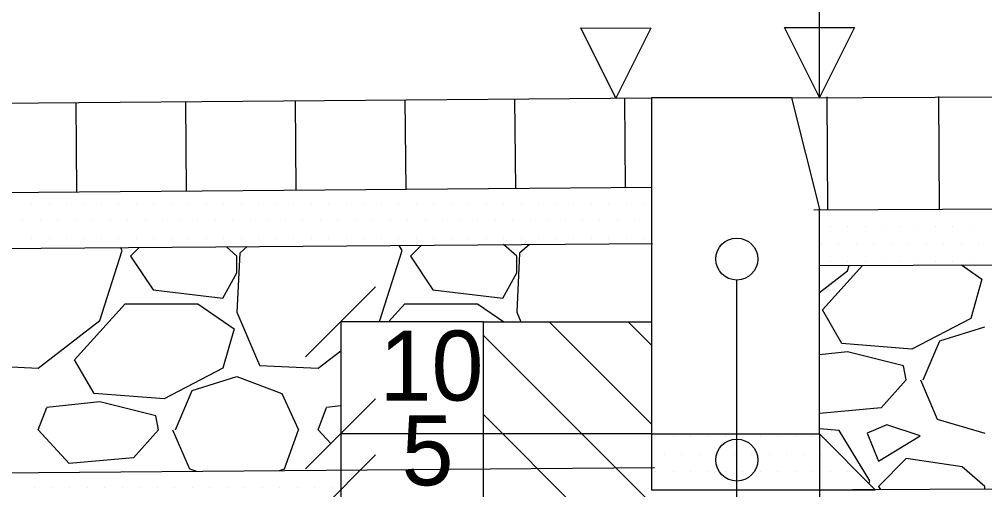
# Model space of a CAD drawing. Extents: x -219625893 to 7498339, y 5791790 to 5792761.
# Drawn here: x 7495350.16 to 7495367.41, y 5791866.2 to 5791874.6 of the extents above; entities that cross this region are included whole.
import ezdxf

# ---------------------------------------------------------------- set-up
doc = ezdxf.new("R2010")
doc.units = 0
for name, color, linetype in [('D_kons_wyp_kruszywo_lamane', 7, 'Continuous'), ('D_kons_wyp_podsypka_cem-piask', 7, 'Continuous'), ('D_kons_wyp_pospolka', 7, 'Continuous'), ('D_robocze_1', 7, 'Continuous'), ('D_wymiary_500', 7, 'Continuous'), ('Level 1', 7, 'Continuous'), ('Level 10', 7, 'Continuous'), ('Level 8', 7, 'Continuous'), ('wymiary', 7, 'Continuous')]:
    doc.layers.add(name, color=color, linetype=linetype)

msp = doc.modelspace()

# ---------------------------------------------------------------- linework, layer by layer
at = {"layer": 'D_kons_wyp_kruszywo_lamane'}
msp.add_line((7495364.582, 5791867.09), (7495364.567, 5791867.091), dxfattribs=at)
at = {"layer": 'D_kons_wyp_podsypka_cem-piask'}
for p, q in [((7495350.383, 5791871.318), (7495350.383, 5791871.318)), ((7495350.695, 5791871.318), (7495350.695, 5791871.318)), ((7495351.008, 5791871.318), (7495351.008, 5791871.318)), ((7495351.32, 5791871.318), (7495351.32, 5791871.318)), ((7495351.633, 5791871.318), (7495351.633, 5791871.318)), ((7495351.945, 5791871.318), (7495351.945, 5791871.318)), ((7495352.258, 5791871.318), (7495352.258, 5791871.318)), ((7495352.57, 5791871.318), (7495352.57, 5791871.318)), ((7495352.883, 5791871.318), (7495352.883, 5791871.318)), ((7495353.195, 5791871.318), (7495353.195, 5791871.318)), ((7495353.508, 5791871.318), (7495353.508, 5791871.318)), ((7495353.82, 5791871.318), (7495353.82, 5791871.318)), ((7495354.133, 5791871.318), (7495354.133, 5791871.318)), ((7495354.445, 5791871.318), (7495354.445, 5791871.318)), ((7495354.758, 5791871.318), (7495354.758, 5791871.318)), ((7495355.07, 5791871.318), (7495355.07, 5791871.318)), ((7495355.383, 5791871.318), (7495355.383, 5791871.318)), ((7495355.695, 5791871.318), (7495355.695, 5791871.318)), ((7495356.008, 5791871.318), (7495356.008, 5791871.318)), ((7495356.32, 5791871.318), (7495356.32, 5791871.318)), ((7495356.633, 5791871.318), (7495356.633, 5791871.318)), ((7495356.945, 5791871.318), (7495356.945, 5791871.318)), ((7495357.258, 5791871.318), (7495357.258, 5791871.318)), ((7495357.57, 5791871.318), (7495357.57, 5791871.318)), ((7495357.883, 5791871.318), (7495357.883, 5791871.318)), ((7495358.195, 5791871.318), (7495358.195, 5791871.318)), ((7495358.508, 5791871.318), (7495358.508, 5791871.318)), ((7495358.82, 5791871.318), (7495358.82, 5791871.318)), ((7495359.133, 5791871.318), (7495359.133, 5791871.318)), ((7495359.445, 5791871.318), (7495359.445, 5791871.318)), ((7495359.758, 5791871.318), (7495359.758, 5791871.318)), ((7495360.07, 5791871.318), (7495360.07, 5791871.318)), ((7495360.383, 5791871.318), (7495360.383, 5791871.318)), ((7495360.695, 5791871.318), (7495360.695, 5791871.318)), ((7495361.008, 5791871.318), (7495361.008, 5791871.318)), ((7495361.32, 5791871.318), (7495361.32, 5791871.318)), ((7495364.494, 5791871.207), (7495364.494, 5791871.207)), ((7495364.807, 5791871.207), (7495364.807, 5791871.207)), ((7495365.119, 5791871.207), (7495365.119, 5791871.207)), ((7495365.432, 5791871.207), (7495365.432, 5791871.207)), ((7495365.744, 5791871.207), (7495365.744, 5791871.207)), ((7495366.057, 5791871.207), (7495366.057, 5791871.207)), ((7495366.369, 5791871.207), (7495366.369, 5791871.207)), ((7495366.682, 5791871.207), (7495366.682, 5791871.207)), ((7495366.994, 5791871.207), (7495366.994, 5791871.207)), ((7495367.307, 5791871.207), (7495367.307, 5791871.207)), ((7495350.227, 5791871.005), (7495350.227, 5791871.005)), ((7495350.539, 5791871.005), (7495350.539, 5791871.005)), ((7495350.852, 5791871.005), (7495350.852, 5791871.005)), ((7495351.164, 5791871.005), (7495351.164, 5791871.005)), ((7495351.477, 5791871.005), (7495351.477, 5791871.005)), ((7495351.789, 5791871.005), (7495351.789, 5791871.005)), ((7495352.102, 5791871.005), (7495352.102, 5791871.005)), ((7495352.414, 5791871.005), (7495352.414, 5791871.005)), ((7495352.727, 5791871.005), (7495352.727, 5791871.005)), ((7495353.039, 5791871.005), (7495353.039, 5791871.005)), ((7495353.352, 5791871.005), (7495353.352, 5791871.005)), ((7495353.664, 5791871.005), (7495353.664, 5791871.005)), ((7495353.977, 5791871.005), (7495353.977, 5791871.005)), ((7495354.289, 5791871.005), (7495354.289, 5791871.005)), ((7495354.602, 5791871.005), (7495354.602, 5791871.005)), ((7495354.914, 5791871.005), (7495354.914, 5791871.005)), ((7495355.227, 5791871.005), (7495355.227, 5791871.005)), ((7495355.539, 5791871.005), (7495355.539, 5791871.005)), ((7495355.852, 5791871.005), (7495355.852, 5791871.005)), ((7495356.164, 5791871.005), (7495356.164, 5791871.005)), ((7495356.477, 5791871.005), (7495356.477, 5791871.005)), ((7495356.789, 5791871.005), (7495356.789, 5791871.005)), ((7495357.102, 5791871.005), (7495357.102, 5791871.005)), ((7495357.414, 5791871.005), (7495357.414, 5791871.005)), ((7495357.727, 5791871.005), (7495357.727, 5791871.005)), ((7495358.039, 5791871.005), (7495358.039, 5791871.005)), ((7495358.352, 5791871.005), (7495358.352, 5791871.005)), ((7495358.664, 5791871.005), (7495358.664, 5791871.005)), ((7495358.977, 5791871.005), (7495358.977, 5791871.005)), ((7495359.289, 5791871.005), (7495359.289, 5791871.005)), ((7495359.602, 5791871.005), (7495359.602, 5791871.005)), ((7495359.914, 5791871.005), (7495359.914, 5791871.005)), ((7495360.227, 5791871.005), (7495360.227, 5791871.005)), ((7495360.539, 5791871.005), (7495360.539, 5791871.005)), ((7495360.852, 5791871.005), (7495360.852, 5791871.005)), ((7495361.164, 5791871.005), (7495361.164, 5791871.005)), ((7495364.651, 5791870.894), (7495364.651, 5791870.894)), ((7495364.963, 5791870.894), (7495364.963, 5791870.894)), ((7495365.276, 5791870.894), (7495365.276, 5791870.894)), ((7495365.588, 5791870.894), (7495365.588, 5791870.894)), ((7495365.901, 5791870.894), (7495365.901, 5791870.894)), ((7495366.213, 5791870.894), (7495366.213, 5791870.894)), ((7495366.526, 5791870.894), (7495366.526, 5791870.894)), ((7495366.838, 5791870.894), (7495366.838, 5791870.894)), ((7495367.151, 5791870.894), (7495367.151, 5791870.894)), ((7495350.383, 5791870.693), (7495350.383, 5791870.693)), ((7495350.695, 5791870.693), (7495350.695, 5791870.693)), ((7495351.008, 5791870.693), (7495351.008, 5791870.693)), ((7495351.32, 5791870.693), (7495351.32, 5791870.693)), ((7495351.633, 5791870.693), (7495351.633, 5791870.693)), ((7495351.945, 5791870.693), (7495351.945, 5791870.693)), ((7495352.258, 5791870.693), (7495352.258, 5791870.693)), ((7495352.57, 5791870.693), (7495352.57, 5791870.693)), ((7495352.883, 5791870.693), (7495352.883, 5791870.693)), ((7495353.195, 5791870.693), (7495353.195, 5791870.693)), ((7495353.508, 5791870.693), (7495353.508, 5791870.693)), ((7495353.82, 5791870.693), (7495353.82, 5791870.693)), ((7495354.133, 5791870.693), (7495354.133, 5791870.693)), ((7495354.445, 5791870.693), (7495354.445, 5791870.693)), ((7495354.758, 5791870.693), (7495354.758, 5791870.693)), ((7495355.07, 5791870.693), (7495355.07, 5791870.693)), ((7495355.383, 5791870.693), (7495355.383, 5791870.693)), ((7495355.695, 5791870.693), (7495355.695, 5791870.693)), ((7495356.008, 5791870.693), (7495356.008, 5791870.693)), ((7495356.32, 5791870.693), (7495356.32, 5791870.693)), ((7495356.633, 5791870.693), (7495356.633, 5791870.693)), ((7495356.945, 5791870.693), (7495356.945, 5791870.693)), ((7495357.258, 5791870.693), (7495357.258, 5791870.693)), ((7495357.57, 5791870.693), (7495357.57, 5791870.693)), ((7495357.883, 5791870.693), (7495357.883, 5791870.693)), ((7495358.195, 5791870.693), (7495358.195, 5791870.693)), ((7495358.508, 5791870.693), (7495358.508, 5791870.693)), ((7495358.82, 5791870.693), (7495358.82, 5791870.693)), ((7495359.133, 5791870.693), (7495359.133, 5791870.693)), ((7495359.445, 5791870.693), (7495359.445, 5791870.693)), ((7495359.758, 5791870.693), (7495359.758, 5791870.693)), ((7495360.07, 5791870.693), (7495360.07, 5791870.693)), ((7495360.383, 5791870.693), (7495360.383, 5791870.693)), ((7495360.695, 5791870.693), (7495360.695, 5791870.693)), ((7495361.008, 5791870.693), (7495361.008, 5791870.693)), ((7495361.32, 5791870.693), (7495361.32, 5791870.693)), ((7495364.494, 5791870.582), (7495364.494, 5791870.582)), ((7495364.807, 5791870.582), (7495364.807, 5791870.582)), ((7495365.119, 5791870.582), (7495365.119, 5791870.582)), ((7495365.432, 5791870.582), (7495365.432, 5791870.582)), ((7495365.744, 5791870.582), (7495365.744, 5791870.582)), ((7495366.057, 5791870.582), (7495366.057, 5791870.582)), ((7495366.369, 5791870.582), (7495366.369, 5791870.582)), ((7495366.682, 5791870.582), (7495366.682, 5791870.582)), ((7495366.994, 5791870.582), (7495366.994, 5791870.582)), ((7495367.307, 5791870.582), (7495367.307, 5791870.582)), ((7495364.651, 5791870.269), (7495364.651, 5791870.269)), ((7495364.963, 5791870.269), (7495364.963, 5791870.269)), ((7495365.276, 5791870.269), (7495365.276, 5791870.269)), ((7495365.588, 5791870.269), (7495365.588, 5791870.269)), ((7495365.901, 5791870.269), (7495365.901, 5791870.269)), ((7495366.213, 5791870.269), (7495366.213, 5791870.269)), ((7495366.526, 5791870.269), (7495366.526, 5791870.269)), ((7495366.838, 5791870.269), (7495366.838, 5791870.269)), ((7495367.151, 5791870.269), (7495367.151, 5791870.269)), ((7495361.532, 5791867.145), (7495361.532, 5791867.145)), ((7495361.844, 5791867.145), (7495361.844, 5791867.145)), ((7495362.157, 5791867.145), (7495362.157, 5791867.145)), ((7495362.469, 5791867.145), (7495362.469, 5791867.145)), ((7495362.782, 5791867.145), (7495362.782, 5791867.145)), ((7495363.094, 5791867.145), (7495363.094, 5791867.145)), ((7495363.407, 5791867.145), (7495363.407, 5791867.145)), ((7495363.719, 5791867.145), (7495363.719, 5791867.145)), ((7495364.032, 5791867.145), (7495364.032, 5791867.145)), ((7495364.344, 5791867.145), (7495364.344, 5791867.145)), ((7495361.688, 5791866.833), (7495361.688, 5791866.833)), ((7495362, 5791866.833), (7495362, 5791866.833)), ((7495362.313, 5791866.833), (7495362.313, 5791866.833)), ((7495362.625, 5791866.833), (7495362.625, 5791866.833)), ((7495362.938, 5791866.833), (7495362.938, 5791866.833)), ((7495363.25, 5791866.833), (7495363.25, 5791866.833)), ((7495363.563, 5791866.833), (7495363.563, 5791866.833)), ((7495363.875, 5791866.833), (7495363.875, 5791866.833)), ((7495364.188, 5791866.833), (7495364.188, 5791866.833)), ((7495364.5, 5791866.833), (7495364.5, 5791866.833)), ((7495364.813, 5791866.833), (7495364.813, 5791866.833)), ((7495361.532, 5791866.52), (7495361.532, 5791866.52)), ((7495361.844, 5791866.52), (7495361.844, 5791866.52)), ((7495362.157, 5791866.52), (7495362.157, 5791866.52)), ((7495362.469, 5791866.52), (7495362.469, 5791866.52)), ((7495362.782, 5791866.52), (7495362.782, 5791866.52)), ((7495363.094, 5791866.52), (7495363.094, 5791866.52)), ((7495363.407, 5791866.52), (7495363.407, 5791866.52)), ((7495363.719, 5791866.52), (7495363.719, 5791866.52)), ((7495364.032, 5791866.52), (7495364.032, 5791866.52)), ((7495364.344, 5791866.52), (7495364.344, 5791866.52)), ((7495364.657, 5791866.52), (7495364.657, 5791866.52)), ((7495364.969, 5791866.52), (7495364.969, 5791866.52)), ((7495361.688, 5791866.208), (7495361.688, 5791866.208)), ((7495362, 5791866.208), (7495362, 5791866.208)), ((7495362.313, 5791866.208), (7495362.313, 5791866.208)), ((7495362.625, 5791866.208), (7495362.625, 5791866.208)), ((7495362.938, 5791866.208), (7495362.938, 5791866.208)), ((7495363.25, 5791866.208), (7495363.25, 5791866.208)), ((7495363.563, 5791866.208), (7495363.563, 5791866.208)), ((7495363.875, 5791866.208), (7495363.875, 5791866.208)), ((7495364.188, 5791866.208), (7495364.188, 5791866.208)), ((7495364.5, 5791866.208), (7495364.5, 5791866.208)), ((7495364.813, 5791866.208), (7495364.813, 5791866.208)), ((7495365.125, 5791866.208), (7495365.125, 5791866.208)), ((7495365.438, 5791866.208), (7495365.438, 5791866.208))]:
    msp.add_line(p, q, dxfattribs=at)
at = {"layer": 'D_kons_wyp_pospolka'}
for p, q in [((7495359.278, 5791870.582), (7495359.103, 5791870.422)), ((7495351.603, 5791869.222), (7495352.003, 5791870.472)), ((7495352.003, 5791870.472), (7495351.972, 5791870.523)), ((7495352.307, 5791870.526), (7495352.153, 5791870.372)), ((7495354.053, 5791870.372), (7495353.863, 5791870.538)), ((7495354.103, 5791870.422), (7495354.053, 5791869.372)), ((7495354.234, 5791870.541), (7495354.103, 5791870.422)), ((7495356.603, 5791869.222), (7495357.003, 5791870.472)), ((7495357.003, 5791870.472), (7495356.948, 5791870.563)), ((7495357.347, 5791870.566), (7495357.153, 5791870.372)), ((7495359.053, 5791870.372), (7495358.817, 5791870.578)), ((7495359.103, 5791870.422), (7495359.053, 5791869.372)), ((7495352.153, 5791870.372), (7495352.553, 5791869.772)), ((7495354.053, 5791870.072), (7495354.053, 5791870.372)), ((7495357.153, 5791870.372), (7495357.553, 5791869.772)), ((7495359.053, 5791870.072), (7495359.053, 5791870.372)), ((7495353.803, 5791869.622), (7495354.053, 5791870.072)), ((7495358.803, 5791869.622), (7495359.053, 5791870.072)), ((7495364.458, 5791869.722), (7495364.962, 5791870.112)), ((7495364.512, 5791869.411), (7495365.228, 5791870.206)), ((7495364.962, 5791870.111), (7495364.992, 5791870.205)), ((7495366.995, 5791870.215), (7495367.362, 5791869.961)), ((7495367.362, 5791869.961), (7495367.162, 5791869.261)), ((7495352.553, 5791869.772), (7495353.803, 5791869.622)), ((7495357.553, 5791869.772), (7495358.803, 5791869.622)), ((7495351.153, 5791868.522), (7495352.053, 5791869.522)), ((7495352.053, 5791869.522), (7495353.353, 5791869.522)), ((7495353.353, 5791869.522), (7495354.003, 5791869.072)), ((7495354.053, 5791869.373), (7495354.453, 5791868.423)), ((7495356.762, 5791869.199), (7495357.053, 5791869.522)), ((7495357.053, 5791869.522), (7495358.353, 5791869.522)), ((7495358.353, 5791869.522), (7495358.819, 5791869.199)), ((7495359.053, 5791869.373), (7495359.126, 5791869.199)), ((7495364.862, 5791868.811), (7495364.512, 5791869.411)), ((7495350.503, 5791868.372), (7495351.603, 5791869.222)), ((7495356.574, 5791869.199), (7495356.603, 5791869.222)), ((7495367.162, 5791869.261), (7495366.112, 5791868.711)), ((7495354.003, 5791869.072), (7495353.803, 5791868.372)), ((7495366.612, 5791868.861), (7495367.412, 5791869.111)), ((7495366.312, 5791868.161), (7495366.612, 5791868.861)), ((7495355.503, 5791868.372), (7495355.906, 5791868.683)), ((7495366.112, 5791868.711), (7495364.862, 5791868.811)), ((7495351.503, 5791867.922), (7495351.153, 5791868.522)), ((7495364.962, 5791868.661), (7495364.458, 5791868.608)), ((7495365.962, 5791868.411), (7495364.962, 5791868.661)), ((7495349.453, 5791868.422), (7495350.503, 5791868.372)), ((7495353.803, 5791868.372), (7495352.753, 5791867.822)), ((7495354.453, 5791868.422), (7495355.503, 5791868.372)), ((7495366.012, 5791868.161), (7495365.962, 5791868.411)), ((7495353.253, 5791867.972), (7495354.053, 5791868.222)), ((7495354.053, 5791868.222), (7495354.853, 5791867.922)), ((7495366.012, 5791868.161), (7495365.562, 5791867.661)), ((7495366.263, 5791868.161), (7495366.563, 5791867.461)), ((7495352.753, 5791867.822), (7495351.503, 5791867.922)), ((7495352.953, 5791867.272), (7495353.253, 5791867.972)), ((7495354.853, 5791867.922), (7495355.153, 5791867.272)), ((7495350.503, 5791867.272), (7495350.653, 5791867.672)), ((7495351.603, 5791867.772), (7495350.653, 5791867.672)), ((7495352.603, 5791867.522), (7495351.603, 5791867.772)), ((7495355.503, 5791867.272), (7495355.653, 5791867.672)), ((7495355.906, 5791867.699), (7495355.653, 5791867.672)), ((7495365.562, 5791867.661), (7495364.458, 5791867.565)), ((7495352.653, 5791867.272), (7495352.603, 5791867.522)), ((7495365.662, 5791867.361), (7495365.312, 5791867.211)), ((7495366.262, 5791867.161), (7495365.662, 5791867.361)), ((7495366.562, 5791867.461), (7495367.412, 5791867.211)), ((7495351.053, 5791866.672), (7495350.503, 5791867.272)), ((7495352.653, 5791867.272), (7495352.203, 5791866.772)), ((7495352.903, 5791867.272), (7495353.203, 5791866.572)), ((7495354.903, 5791866.572), (7495355.153, 5791867.272)), ((7495355.73, 5791867.024), (7495355.503, 5791867.272)), ((7495364.812, 5791867.261), (7495364.458, 5791867.29)), ((7495365.362, 5791866.361), (7495364.812, 5791867.261)), ((7495365.312, 5791867.211), (7495365.512, 5791866.711)), ((7495365.512, 5791866.711), (7495366.262, 5791867.161)), ((7495352.203, 5791866.772), (7495351.053, 5791866.672)), ((7495366.012, 5791866.761), (7495365.512, 5791866.261)), ((7495367.012, 5791866.611), (7495366.012, 5791866.761)), ((7495353.203, 5791866.572), (7495353.332, 5791866.534)), ((7495354.814, 5791866.546), (7495354.903, 5791866.572)), ((7495367.412, 5791866.261), (7495367.012, 5791866.611)), ((7495365.346, 5791866.311), (7495365.362, 5791866.361)), ((7495350.439, 5791866.244), (7495350.439, 5791866.244)), ((7495350.752, 5791866.244), (7495350.752, 5791866.244)), ((7495351.064, 5791866.244), (7495351.064, 5791866.244)), ((7495351.377, 5791866.244), (7495351.377, 5791866.244)), ((7495351.689, 5791866.244), (7495351.689, 5791866.244)), ((7495352.002, 5791866.244), (7495352.002, 5791866.244)), ((7495352.314, 5791866.244), (7495352.314, 5791866.244)), ((7495352.627, 5791866.244), (7495352.627, 5791866.244)), ((7495352.939, 5791866.244), (7495352.939, 5791866.244)), ((7495353.252, 5791866.244), (7495353.252, 5791866.244)), ((7495353.564, 5791866.244), (7495353.564, 5791866.244)), ((7495353.877, 5791866.244), (7495353.877, 5791866.244)), ((7495354.189, 5791866.244), (7495354.189, 5791866.244)), ((7495354.502, 5791866.244), (7495354.502, 5791866.244)), ((7495354.814, 5791866.244), (7495354.814, 5791866.244)), ((7495355.127, 5791866.244), (7495355.127, 5791866.244)), ((7495355.439, 5791866.244), (7495355.439, 5791866.244)), ((7495355.752, 5791866.244), (7495355.752, 5791866.244)), ((7495365.512, 5791866.261), (7495365.548, 5791866.207)), ((7495367.412, 5791866.217), (7495367.412, 5791866.261))]:
    msp.add_line(p, q, dxfattribs=at)
at = {"layer": 'D_robocze_1'}
for p, q in [((7495361.458, 5791867.371), (7495359.63, 5791869.199)), ((7495361.458, 5791868.785), (7495361.044, 5791869.199)), ((7495364.216, 5791863.199), (7495358.458, 5791868.957)), ((7495362.801, 5791863.199), (7495358.458, 5791867.543))]:
    msp.add_line(p, q, dxfattribs=at)
at = {"layer": 'D_wymiary_500'}
for p, q in [((7495364.458, 5791873.199), (7495364.458, 5791895.3)), ((7495364.458, 5791870.202), (7495414.458, 5791870.452)), ((7495358.458, 5791869.199), (7495355.906, 5791869.199)), ((7495355.906, 5791869.199), (7495355.906, 5791863.199)), ((7495361.458, 5791867.199), (7495355.906, 5791867.199)), ((7495364.458, 5791867.199), (7495364.458, 5791859.316)), ((7495365.053, 5791866.205), (7495414.458, 5791866.452))]:
    msp.add_line(p, q, dxfattribs=at)
at = {"layer": 'Level 1'}
for p, q in [((7495360.823, 5791873.194), (7495360.199, 5791874.445)), ((7495360.199, 5791874.445), (7495361.449, 5791874.444)), ((7495361.449, 5791874.444), (7495360.823, 5791873.194)), ((7495364.458, 5791873.202), (7495363.834, 5791874.452)), ((7495363.834, 5791874.452), (7495365.084, 5791874.451)), ((7495365.084, 5791874.451), (7495364.458, 5791873.202))]:
    msp.add_line(p, q, dxfattribs=at)
at = {"layer": 'Level 10'}
for p, q in [((7495363.961, 5791873.199), (7495414.458, 5791873.452)), ((7495298.458, 5791872.694), (7495361.458, 5791873.199)), ((7495359.033, 5791871.58), (7495359.02, 5791873.18)), ((7495360.993, 5791871.596), (7495360.98, 5791873.19)), ((7495363.961, 5791873.199), (7495364.458, 5791871.212)), ((7495364.608, 5791871.203), (7495364.598, 5791873.214)), ((7495366.602, 5791871.213), (7495366.592, 5791873.224)), ((7495351.192, 5791871.517), (7495351.18, 5791873.117)), ((7495353.153, 5791871.533), (7495353.14, 5791873.133)), ((7495355.113, 5791871.549), (7495355.1, 5791873.148)), ((7495357.073, 5791871.564), (7495357.06, 5791873.164)), ((7495298.461, 5791871.094), (7495361.471, 5791871.6)), ((7495364.361, 5791871.201), (7495414.466, 5791871.452))]:
    msp.add_line(p, q, dxfattribs=at)
at = {"layer": 'Level 8'}
for p, q in [((7495363.961, 5791873.199), (7495361.458, 5791873.199)), ((7495361.458, 5791873.199), (7495361.458, 5791867.199)), ((7495364.458, 5791867.199), (7495364.458, 5791871.212)), ((7495358.458, 5791863.199), (7495358.458, 5791869.199)), ((7495358.458, 5791869.199), (7495361.458, 5791869.199)), ((7495361.458, 5791867.199), (7495364.458, 5791867.199)), ((7495364.458, 5791867.199), (7495365.458, 5791866.199))]:
    msp.add_line(p, q, dxfattribs=at)
msp.add_lwpolyline([(7495361.458, 5791867.199), (7495361.458, 5791866.199), (7495365.458, 5791866.199)], dxfattribs=at)
at = {"layer": 'wymiary'}
for p, q in [((7495298.462, 5791870.094), (7495361.479, 5791870.6)), ((7495362.983, 5791843.439), (7495362.983, 5791869.945)), ((7495355.28, 5791868.575), (7495356.531, 5791869.824)), ((7495355.28, 5791866.575), (7495356.531, 5791867.824)), ((7495355.28, 5791865.575), (7495356.531, 5791866.824)), ((7495298.468, 5791866.094), (7495361.511, 5791866.6))]:
    msp.add_line(p, q, dxfattribs=at)
for centre in [(7495362.983, 5791870.32), (7495362.983, 5791866.731)]:
    msp.add_circle(centre, 0.375, dxfattribs=at)

# ---------------------------------------------------------------- texts
at = {"layer": 'D_wymiary_500'}
for s, p in [('10', (7495356.599, 5791867.792)), ('5', (7495356.993, 5791866.28))]:
    msp.add_text(s, height=1.25, rotation=0.0429, dxfattribs=at).set_placement(p)

doc.saveas('drawing.dxf')
